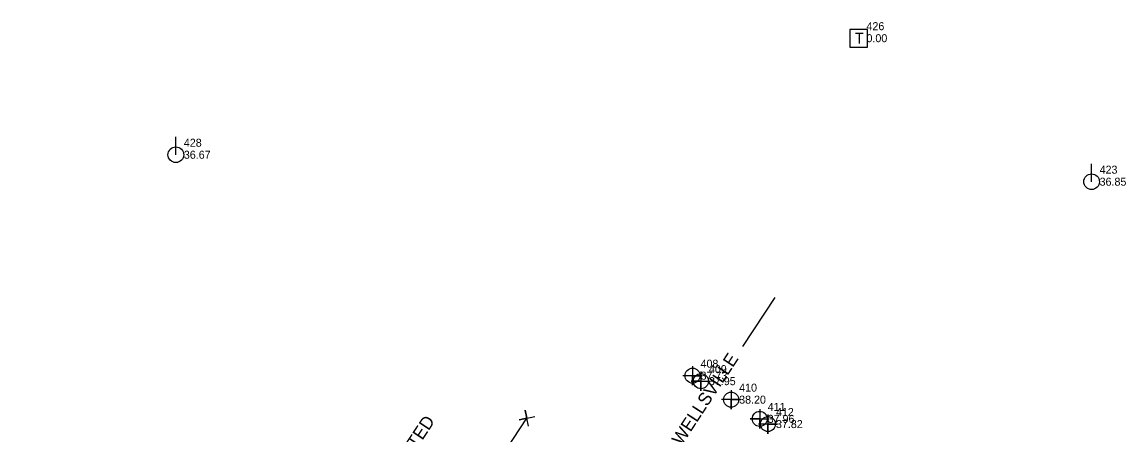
# Model space of a CAD drawing. Extents: x 2603627 to 2605187, y 896619 to 899063.
# Drawn here: x 2604841.7 to 2605186.6, y 898934.1 to 899063.1 of the extents above; entities that cross this region are included whole.
import ezdxf

# ---------------------------------------------------------------- set-up
doc = ezdxf.new("R2010")
doc.units = 0
for name, color, linetype in [('Exist DTM Crownline Cogo Point CELL', 7, 'Continuous'), ('Exist Other Culture Area Outline Text', 7, 'Continuous'), ('Exist Property Corner CELL', 7, 'Continuous'), ('Exist Right of Way Line', 7, 'Continuous'), ('Exist Roads EOP Cogo Point CELL', 7, 'Continuous'), ('Exist Roads EOP Leader', 7, 'Continuous'), ('Exist Roads EOP Text', 7, 'Continuous'), ('Exist Roads EOT Cogo Point CELL', 7, 'Continuous'), ('Exist Utilities Power Pole CELL', 7, 'Continuous'), ('Exist Utilities Power Pole Cogo Elevation', 7, 'Continuous'), ('Exist Utilities Power Pole Cogo Number', 7, 'Continuous'), ('Exist Utilities Telephone Pedestal CELL', 7, 'Continuous'), ('Scratch_Level_1', 7, 'Continuous')]:
    doc.layers.add(name, color=color, linetype=linetype)

# ---------------------------------------------------------------- blocks, each defined once
blk = doc.blocks.new('EXIST ROADS EOP COGO POINT')
at = {"layer": 'Exist Roads EOP Cogo Point CELL'}
blk.add_lwpolyline([(0, 0.06), (0, -0.06), (0, 0), (0.06, 0), (-0.06, 0)], dxfattribs=at)
blk.add_circle((0, 0), 0.0469, dxfattribs=at)
blk = doc.blocks.new('EXIST ROADS EOT COGO POINT')
at = {"layer": 'Exist Roads EOT Cogo Point CELL'}
blk.add_lwpolyline([(0, 0.06), (0, -0.06), (0, 0), (-0.06, 0), (0.06, 0)], dxfattribs=at)
blk.add_circle((0, 0), 0.0469, dxfattribs=at)
blk = doc.blocks.new('EXIST DTM CROWNLINE COGO POINT')
at = {"layer": 'Exist DTM Crownline Cogo Point CELL'}
blk.add_lwpolyline([(0, 0.06), (0, -0.06), (0, 0), (0.06, 0), (-0.06, 0)], dxfattribs=at)
blk.add_circle((0, 0), 0.0469, dxfattribs=at)
blk = doc.blocks.new('EXIST UTILITIES TELEPHONE PEDESTAL')
at = {"layer": 'Exist Utilities Telephone Pedestal CELL'}
blk.add_line((0, 0), (0, 0), dxfattribs=at)
blk.add_lwpolyline([(-0.0545, -0.0565), (0.0574, -0.0565), (0.0574, 0.0554), (-0.0545, 0.0554), (-0.0545, -0.0565)], dxfattribs=at)
blk.add_text('T', height=0.0684, dxfattribs=at).set_placement((-0.0226, -0.0343))

msp = doc.modelspace()

# ---------------------------------------------------------------- linework, layer by layer
at = {"layer": 'Exist Property Corner CELL'}
msp.add_line((2604999.42, 898939.36), (2604999.42, 898939.36), dxfattribs=at)
msp.add_lwpolyline([(2604999.92, 898936.91), (2604998.93, 898941.81), (2604999.42, 898939.36), (2604996.97, 898938.86), (2605001.87, 898939.85)], dxfattribs=at)
at = {"layer": 'Exist Right of Way Line'}
msp.add_line((2604639.76, 898396.41), (2604999.42, 898939.36), dxfattribs=at)
at = {"layer": 'Exist Roads EOP Leader'}
msp.add_line((2605076.88, 898977.03), (2605066.75, 898961.79), dxfattribs=at)
at = {"layer": 'Exist Utilities Power Pole CELL'}
for p, q in [((2604889.75, 899021.64), (2604889.75, 899027.26)), ((2604889.75, 899021.64), (2604889.75, 899021.64)), ((2605175.87, 899013.22), (2605175.87, 899018.85)), ((2605175.87, 899013.22), (2605175.87, 899013.22))]:
    msp.add_line(p, q, dxfattribs=at)
for centre in [(2604889.75, 899021.64), (2605175.87, 899013.22)]:
    msp.add_circle(centre, 2.45, dxfattribs=at)

# ---------------------------------------------------------------- block references
at = {"layer": 'Scratch_Level_1', "xscale": 50, "yscale": 50}
for name, p in [('EXIST UTILITIES TELEPHONE PEDESTAL', (2605103.03, 899058.04)), ('EXIST ROADS EOP COGO POINT', (2605051.19, 898952.63)), ('EXIST ROADS EOT COGO POINT', (2605053.8, 898950.92)), ('EXIST DTM CROWNLINE COGO POINT', (2605063.25, 898945.14)), ('EXIST ROADS EOT COGO POINT', (2605072.17, 898939.14)), ('EXIST ROADS EOP COGO POINT', (2605074.75, 898937.52))]:
    msp.add_blockref(name, p, dxfattribs=at)

# ---------------------------------------------------------------- texts
at = {"layer": 'Exist Other Culture Area Outline Text'}
msp.add_text('CULTIVATED', height=4, rotation=56.4786, dxfattribs=at).set_placement((2604952.48, 898910.72))
at = {"layer": 'Exist Roads EOP Text'}
msp.add_text('TO POWELLSVILLE', height=4, rotation=56.7676, dxfattribs=at).set_placement((2605038.66, 898916.7))
at = {"layer": 'Exist Utilities Power Pole Cogo Elevation'}
for s, p in [('36.67', (2604892.25, 899020.39)), ('36.85', (2605178.37, 899011.97))]:
    msp.add_text(s, height=2.5, dxfattribs=at).set_placement(p)
at = {"layer": 'Exist Utilities Power Pole Cogo Number'}
for s, p in [('428', (2604892.25, 899024.14)), ('423', (2605178.37, 899015.72))]:
    msp.add_text(s, height=2.5, dxfattribs=at).set_placement(p)
at = {"layer": 'Scratch_Level_1'}
for s, p in [('426', (2605105.53, 899060.54)), ('0.00', (2605105.53, 899056.79)), ('408', (2605053.69, 898955.13)), ('37.73', (2605053.69, 898951.38)), ('409', (2605056.3, 898953.42)), ('37.95', (2605056.3, 898949.67)), ('410', (2605065.75, 898947.64)), ('38.20', (2605065.75, 898943.89)), ('411', (2605074.67, 898941.64)), ('37.96', (2605074.67, 898937.89)), ('412', (2605077.25, 898940.02)), ('37.82', (2605077.25, 898936.27))]:
    msp.add_text(s, height=2.5, dxfattribs=at).set_placement(p)

doc.saveas('drawing.dxf')
